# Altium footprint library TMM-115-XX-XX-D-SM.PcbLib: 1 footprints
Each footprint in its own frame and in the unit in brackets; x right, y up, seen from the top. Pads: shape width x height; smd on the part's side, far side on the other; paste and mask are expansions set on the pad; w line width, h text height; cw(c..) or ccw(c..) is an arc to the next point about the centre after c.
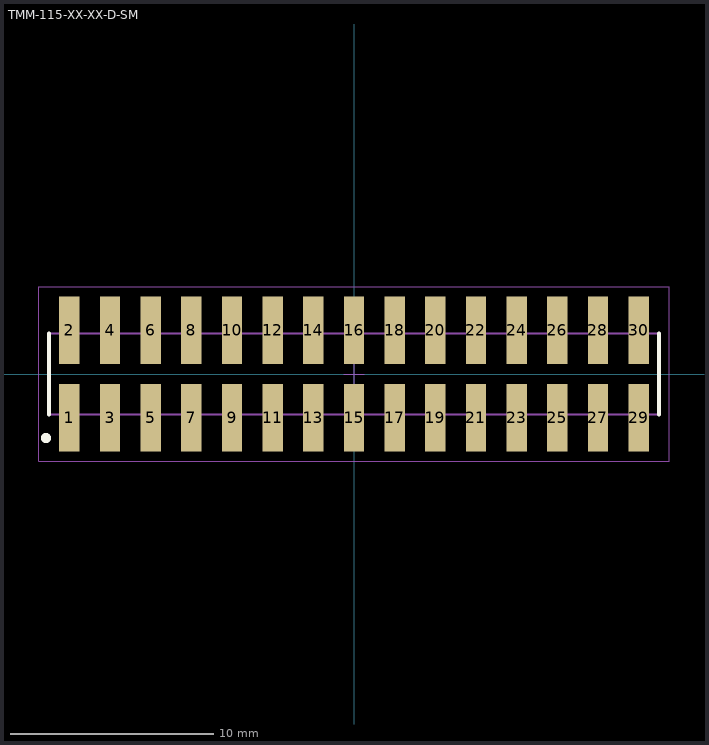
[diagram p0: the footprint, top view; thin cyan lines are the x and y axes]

## TMM-115-XX-XX-D-SM [mm] "2.00mm pitch, 30 pin, terminal strip; double row, SMT"
height 2.77
pads (30):
  rect 1x3.3 smd mask+0: 1(-14,-2.15) 2(-14,2.15) 3(-12,-2.15) 4(-12,2.15) 5(-10,-2.15) 6(-10,2.15) 7(-8,-2.15) 8(-8,2.15) 9(-6,-2.15) 10(-6,2.15) 11(-4,-2.15) 12(-4,2.15) 13(-2,-2.15) 14(-2,2.15) 15(0,-2.15) 16(0,2.15) 17(2,-2.15) 18(2,2.15) 19(4,-2.15) 20(4,2.15) 21(6,-2.15) 22(6,2.15) 23(8,-2.15) 24(8,2.15) 25(10,-2.15) 26(10,2.15) 27(12,-2.15) 28(12,2.15) 29(14,-2.15) 30(14,2.15)
Top Overlay:
  circle w0.25: c-15.15,-3.15 r0.125
  lines w0.2: -15,-2 -15,2 ; 15,-2 15,2
Mechanical 12:
  lines w0.001: -15,-2 -15,2 15,2 15,-2 -15,-2
Mechanical 13:
  lines w0.1: -15,-2 -15,2 15,2 15,-2 -15,-2
  text ".Designator" at 0,-0.127 h1.52
Mechanical 15:
  lines w0.05: -0.5,0 0.5,0 ; 0,-0.5 0,0.5 ; -15.5,-4.3 -15.5,4.3 15.5,4.3 15.5,-4.3 -15.5,-4.3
